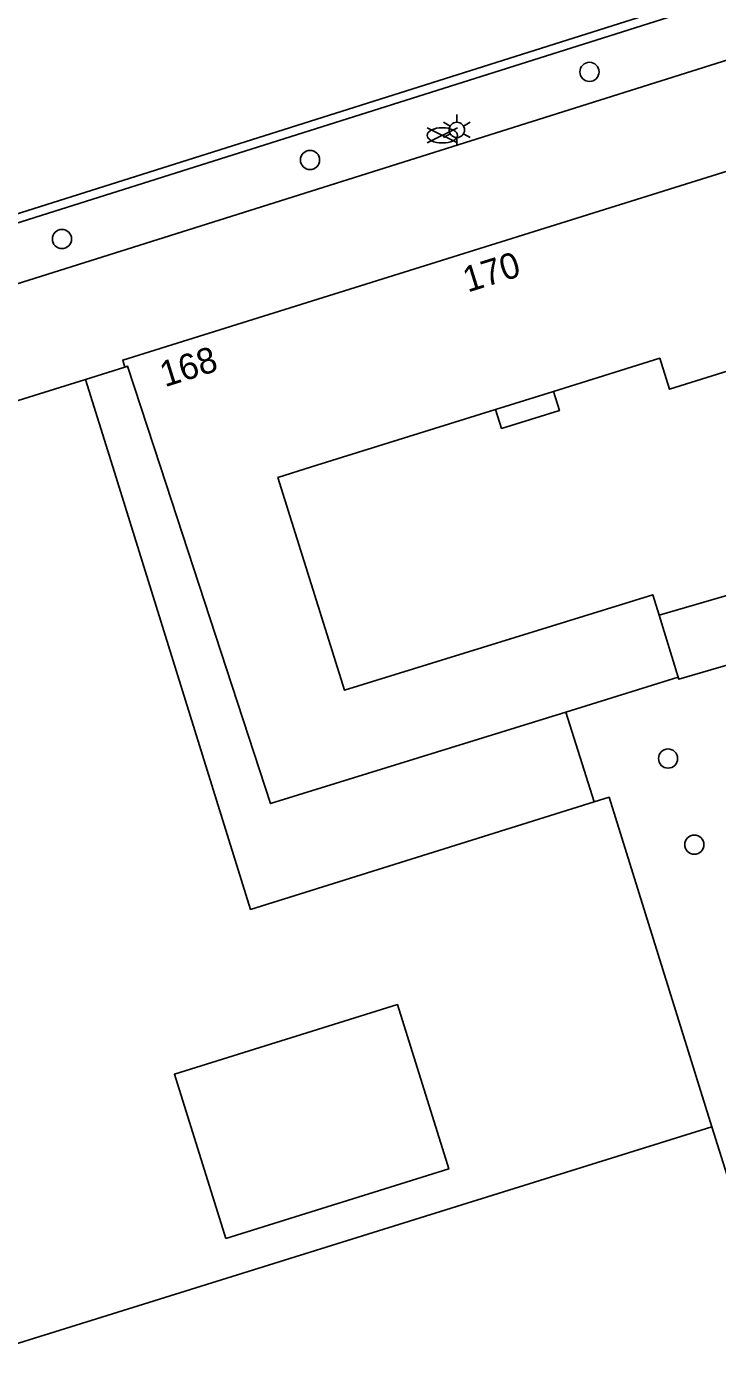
# Model space of a CAD drawing. Extents: x 122462 to 123306, y 485548 to 486417.
# Drawn here: x 122661.2 to 122701.5, y 486198.4 to 486275.7 of the extents above; entities that cross this region are included whole.
import ezdxf

# ---------------------------------------------------------------- set-up
doc = ezdxf.new("R2010")
doc.units = 0
for name, color, linetype in [('Level 1', 7, 'Continuous'), ('Level 15', 7, 'Continuous'), ('Level 17', 7, 'Continuous'), ('Level 23', 7, 'Continuous'), ('Level 30', 7, 'Continuous'), ('Level 4', 7, 'Continuous'), ('Level 5', 7, 'Continuous'), ('Level 50', 7, 'Continuous'), ('Level 52', 7, 'Continuous'), ('Level 53', 7, 'Continuous'), ('Level 58', 7, 'Continuous')]:
    doc.layers.add(name, color=color, linetype=linetype)

msp = doc.modelspace()

# ---------------------------------------------------------------- linework, layer by layer
at = {"layer": 'Level 1'}
for p, q in [((122691.94, 486254.41), (122688.566, 486253.355)), ((122699.226, 486237.726), (122692.671, 486235.696)), ((122701.191, 486211.491), (122702.294, 486207.955))]:
    msp.add_line(p, q, dxfattribs=at)
for points in [[(122666.92, 486255.829), (122666.799, 486256.239), (122712.895, 486270.644), (122723.6, 486273.989)], [(122726.631, 486262.743), (122715.62, 486259.303), (122715.473, 486259.774), (122698.709, 486254.535), (122698.143, 486256.348), (122691.94, 486254.41)], [(122668.998, 486250), (122667.078, 486255.88), (122666.92, 486255.829)], [(122651.459, 486250), (122651.655, 486250.061), (122651.37, 486250.979), (122664.62, 486255.11)], [(122664.62, 486255.11), (122666.213, 486250)], [(122688.566, 486253.355), (122677.825, 486250)], [(122666.213, 486250), (122674.26, 486224.178), (122694.312, 486230.446)], [(122692.671, 486235.696), (122675.415, 486230.354), (122668.998, 486250)], [(122677.825, 486250), (122675.856, 486249.385), (122679.736, 486236.97), (122697.735, 486242.543), (122698.105, 486241.345)], [(122698.105, 486241.345), (122704.857, 486243.315), (122704.175, 486245.515)], [(122707.472, 486240.007), (122699.259, 486237.61), (122699.226, 486237.726)], [(122694.312, 486230.446), (122695.191, 486230.721), (122701.191, 486211.491)], [(122672.809, 486204.96), (122669.816, 486214.553), (122682.834, 486218.623), (122685.827, 486209.029), (122672.809, 486204.96)]]:
    msp.add_lwpolyline(points, dxfattribs=at)
at = {"layer": 'Level 15'}
for points in [[(122647.698, 486260.681), (122684.849, 486272.428), (122757.048, 486295.256)], [(122725.93, 486284.893), (122710.139, 486279.9), (122647.848, 486260.204), (122647.698, 486260.681)]]:
    msp.add_lwpolyline(points, dxfattribs=at)
at = {"layer": 'Level 17'}
msp.add_lwpolyline([(122647.698, 486260.681), (122647.254, 486260.541), (122648.404, 486256.843), (122711.12, 486276.603), (122725.537, 486281.145), (122725.675, 486281.196), (122725.808, 486281.26), (122725.933, 486281.337), (122726.05, 486281.426), (122726.158, 486281.526), (122726.256, 486281.637), (122726.343, 486281.756), (122726.417, 486281.883), (122726.478, 486282.017), (122726.527, 486282.156), (122726.561, 486282.299), (122726.581, 486282.445), (122726.586, 486282.592), (122726.578, 486282.739), (122726.554, 486282.885), (122726.517, 486283.027), (122725.93, 486284.893)], dxfattribs=at)
at = {"layer": 'Level 23'}
for p, q in [((122664.62, 486255.11), (122666.92, 486255.829)), ((122694.312, 486230.446), (122692.671, 486235.696))]:
    msp.add_line(p, q, dxfattribs=at)
at = {"layer": 'Level 30'}
msp.add_lwpolyline([(122691.94, 486254.41), (122692.285, 486253.305), (122688.911, 486252.25), (122688.566, 486253.355)], dxfattribs=at)
at = {"layer": 'Level 4'}
msp.add_lwpolyline([(122598.733, 486166.119), (122616.481, 486171.641), (122649.613, 486181.978), (122645.797, 486194.208), (122701.191, 486211.491)], dxfattribs=at)
at = {"layer": 'Level 5'}
msp.add_line((122699.226, 486237.726), (122698.105, 486241.345), dxfattribs=at)
at = {"layer": 'Level 50'}
for p, q in [((122685.911, 486269.9), (122685.521, 486270.125)), ((122686.301, 486270.125), (122686.301, 486270.575)), ((122687.08, 486270.125), (122686.69, 486269.9)), ((122685.911, 486269.45), (122685.521, 486269.225)), ((122686.301, 486268.775), (122686.301, 486269.225)), ((122687.08, 486269.225), (122686.69, 486269.45))]:
    msp.add_line(p, q, dxfattribs=at)
msp.add_circle((122686.301, 486269.675), 0.45, dxfattribs=at)
at = {"layer": 'Level 52'}
for p, q in [((122684.567, 486268.913), (122686.348, 486269.803)), ((122684.567, 486269.803), (122686.348, 486268.913))]:
    msp.add_line(p, q, dxfattribs=at)
msp.add_ellipse((122685.457, 486269.356), major_axis=(0.89, 0), ratio=0.5, dxfattribs=at)
at = {"layer": 'Level 53'}
for centre in [(122694.042, 486273.059), (122677.733, 486267.92), (122663.25, 486263.304), (122698.631, 486232.981), (122700.163, 486227.956)]:
    msp.add_circle(centre, 0.56, dxfattribs=at)

# ---------------------------------------------------------------- texts
at = {"layer": 'Level 58'}
for s, rotation, p in [('170', 17.35369, (122686.938, 486260.177)), ('168', 17.35825, (122669.256, 486254.65))]:
    msp.add_text(s, height=1.5, rotation=rotation, dxfattribs=at).set_placement(p)

doc.saveas('drawing.dxf')
